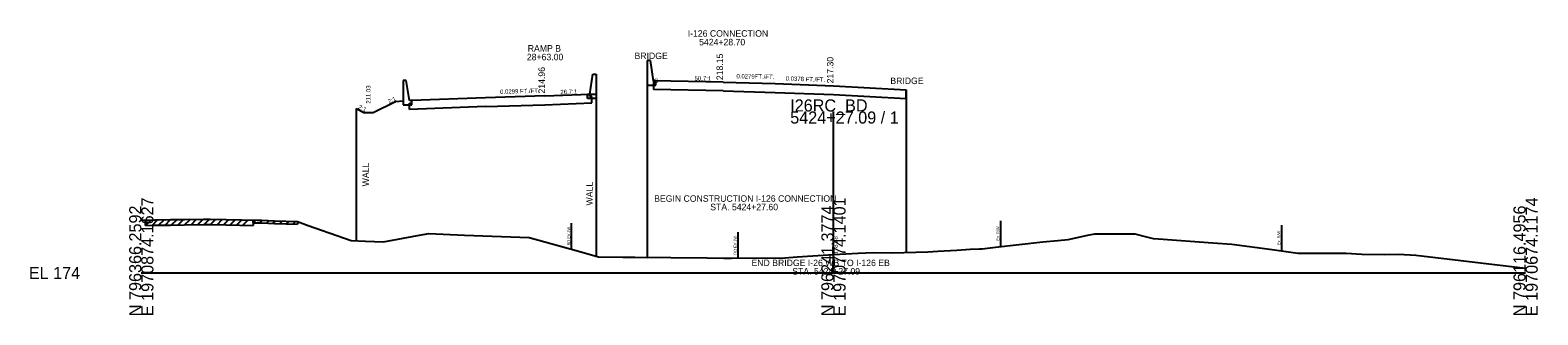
# Model space of a CAD drawing. Extents: x -1417 to 1970873, y -510 to 796304.
# Drawn here: x -1417.4 to -1068.8, y -509.7 to -443.8 of the extents above; entities that cross this region are included whole.
import ezdxf

# ---------------------------------------------------------------- set-up
doc = ezdxf.new("R2010")
doc.units = 0
for name, color, linetype in [('RD_EX_BldgApp', 7, 'Continuous'), ('RD_EX_Conc', 7, 'Continuous'), ('RD_EX_RailRoad', 7, 'Continuous'), ('RD_HC_Cl', 7, 'Continuous'), ('RD_HC_Data', 7, 'Continuous'), ('RD_HC_Data_Tic', 7, 'Continuous'), ('RD_HC_Data_Tic_Rel', 7, 'Continuous'), ('RD_HC_TX_Sta50', 7, 'Continuous'), ('RD_PD_ALT1_LnLine', 7, 'Continuous'), ('RD_PD_ALT1_TrvlWay', 7, 'Continuous'), ('RD_PD_ALT3_CL', 7, 'Continuous'), ('RD_PD_ALT5_CL', 7, 'Continuous'), ('RD_PD_Final_Cl', 7, 'Continuous'), ('RD_PD_Final_LnLine', 7, 'Continuous'), ('RD_PD_Final_TrvlWay', 7, 'Continuous'), ('RD_PD_PaveShd', 7, 'Continuous'), ('RD_Sketch2', 7, 'Continuous'), ('RD_Sketch8', 7, 'Continuous'), ('RD_TX_RoadID', 7, 'Continuous')]:
    doc.layers.add(name, color=color, linetype=linetype)

msp = doc.modelspace()

# ---------------------------------------------------------------- linework, layer by layer
at = {"layer": 'RD_EX_Conc'}
for p, q in [((-1273.99, -450.87), (-1274.74, -450.87)), ((-1274.74, -450.87), (-1274.74, -456.53)), ((-1273.24, -455.53), (-1273.99, -450.87)), ((-1330.41, -455.44), (-1331.16, -455.44)), ((-1331.16, -455.44), (-1331.16, -461.1)), ((-1329.66, -460.1), (-1330.41, -455.44)), ((-1288.02, -458.65), (-1287.27, -453.98)), ((-1287.27, -453.98), (-1286.52, -453.98)), ((-1286.52, -453.98), (-1286.52, -459.65)), ((-1274.74, -456.53), (-1272.74, -456.53)), ((-1272.74, -455.53), (-1273.24, -455.53)), ((-1272.74, -456.53), (-1272.74, -455.53)), ((-1288.52, -459.65), (-1288.52, -458.65)), ((-1288.52, -458.65), (-1288.02, -458.65)), ((-1286.52, -459.65), (-1288.52, -459.65)), ((-1331.16, -461.1), (-1329.16, -461.1)), ((-1329.16, -460.1), (-1329.66, -460.1)), ((-1329.16, -461.1), (-1329.16, -460.1))]:
    msp.add_line(p, q, dxfattribs=at)
at = {"layer": 'RD_HC_Cl'}
for p, q in [((-1231.67, -500), (-1231.67, -462.64)), ((-1391.67, -500), (-1231.67, -500)), ((-1231.67, -500), (-1071.67, -500))]:
    msp.add_line(p, q, dxfattribs=at)
at = {"layer": 'RD_HC_Data'}
for p, q in [((-1390.67, -489.02), (-1390.67, -487.77)), ((-1365.84, -487.76), (-1365.84, -489.01)), ((-1365.84, -488.39), (-1365.84, -487.76)), ((-1390.67, -489.02), (-1388.52, -488.97)), ((-1388.52, -488.97), (-1384.93, -488.91)), ((-1384.93, -488.91), (-1381.71, -488.86)), ((-1381.71, -488.86), (-1377.33, -488.81)), ((-1377.33, -488.81), (-1376.29, -488.8)), ((-1376.29, -488.8), (-1375.74, -488.81)), ((-1375.74, -488.81), (-1372.05, -488.89)), ((-1372.05, -488.89), (-1365.84, -489.01)), ((-1365.84, -488.39), (-1364.89, -488.41)), ((-1364.89, -488.41), (-1363.78, -488.43)), ((-1363.78, -488.43), (-1360.91, -488.52)), ((-1360.91, -488.52), (-1355.54, -488.69)), ((-1355.54, -488.06), (-1355.54, -488.69))]:
    msp.add_line(p, q, dxfattribs=at)
at = {"layer": 'RD_HC_Data_Tic_Rel'}
for p, q in [((-1214.89, -457.6), (-1214.89, -495.22)), ((-1342.04, -461.97), (-1340.04, -462.97)), ((-1338.04, -462.97), (-1340.04, -462.97)), ((-1332.91, -460.4), (-1338.04, -462.97)), ((-1331.16, -460.26), (-1332.91, -460.4))]:
    msp.add_line(p, q, dxfattribs=at)
msp.add_lwpolyline([(-1286.52, -496.12), (-1285.98, -496.28), (-1274.74, -496.39)], dxfattribs=at)
at = {"layer": 'RD_HC_TX_Sta50'}
for p, q in [((-1390.67, -489.02), (-1389.39, -487.74)), ((-1389.17, -488.98), (-1387.9, -487.71)), ((-1387.67, -488.95), (-1386.4, -487.68)), ((-1386.17, -488.93), (-1384.9, -487.65)), ((-1384.67, -488.9), (-1383.41, -487.64)), ((-1383.17, -488.88), (-1381.91, -487.62)), ((-1381.67, -488.86), (-1380.41, -487.6)), ((-1380.17, -488.84), (-1378.91, -487.58)), ((-1378.67, -488.83), (-1377.41, -487.56)), ((-1377.17, -488.81), (-1375.92, -487.55)), ((-1375.67, -488.81), (-1374.45, -487.59)), ((-1374.17, -488.84), (-1372.95, -487.62)), ((-1372.67, -488.87), (-1371.45, -487.65)), ((-1371.17, -488.91), (-1369.95, -487.68)), ((-1369.67, -488.94), (-1368.45, -487.71)), ((-1368.17, -488.97), (-1366.95, -487.74)), ((-1365.84, -488.39), (-1365.21, -487.78)), ((-1364.29, -488.42), (-1363.66, -487.81)), ((-1362.75, -488.46), (-1362.12, -487.86)), ((-1361.2, -488.51), (-1360.58, -487.91)), ((-1359.66, -488.56), (-1359.03, -487.95)), ((-1358.11, -488.61), (-1357.49, -488)), ((-1356.57, -488.65), (-1355.94, -488.05))]:
    msp.add_line(p, q, dxfattribs=at)
at = {"layer": 'RD_PD_ALT1_LnLine'}
for p, q in [((-1193.08, -487.91), (-1193.08, -493.91)), ((-1128.12, -488.91), (-1128.12, -494.91))]:
    msp.add_line(p, q, dxfattribs=at)
at = {"layer": 'RD_PD_ALT1_TrvlWay'}
for p, q in [((-1292.28, -488.46), (-1292.28, -494.46)), ((-1253.8, -490.56), (-1253.8, -496.56))]:
    msp.add_line(p, q, dxfattribs=at)
at = {"layer": 'RD_PD_Final_Cl'}
msp.add_lwpolyline([(-1391.67, -487.8), (-1388.52, -487.72), (-1384.93, -487.66), (-1381.71, -487.61), (-1377.33, -487.56), (-1376.29, -487.55), (-1375.74, -487.56), (-1372.05, -487.64), (-1364.89, -487.78), (-1363.78, -487.8), (-1360.91, -487.9), (-1355.54, -488.06), (-1353.09, -489.03), (-1343.13, -492.48), (-1339.84, -492.63), (-1335.71, -492.82), (-1327.85, -491.3), (-1325.2, -490.86), (-1316.93, -491.27), (-1301.98, -491.78), (-1291.18, -494.77), (-1285.98, -496.28), (-1260.89, -496.53), (-1257.04, -496.57), (-1255.21, -496.57), (-1242.91, -496.51), (-1240.09, -496.24), (-1231.67, -495.72), (-1225.96, -495.38), (-1222.38, -495.27), (-1218.17, -495.31), (-1209.87, -495.09), (-1207.51, -494.96), (-1203.18, -494.72), (-1200.1, -494.53), (-1197.87, -494.41), (-1197.32, -494.39), (-1194.18, -494.04), (-1183.27, -492.81), (-1179.78, -492.47), (-1177.38, -492.26), (-1172.84, -491.28), (-1171.27, -490.95), (-1165.75, -490.94), (-1162.03, -490.93), (-1159.61, -491.54), (-1157.77, -492.02), (-1156.54, -492.08), (-1143.94, -493), (-1139.58, -493.32), (-1130.27, -494.6), (-1124.35, -495.44), (-1122.57, -495.44), (-1113.18, -495.43), (-1109.51, -495.66), (-1104.37, -495.72), (-1101.03, -495.64), (-1097.03, -495.89), (-1071.67, -498.9)], dxfattribs=at)
at = {"layer": 'RD_PD_Final_LnLine'}
for p, q in [((-1257.2, -455.85), (-1273.24, -455.53)), ((-1312.14, -459.45), (-1329.16, -460.1)), ((-1298.37, -459.04), (-1288.02, -458.65)), ((-1231.67, -456.7), (-1214.89, -457.6))]:
    msp.add_line(p, q, dxfattribs=at)
at = {"layer": 'RD_PD_Final_TrvlWay'}
for p, q in [((-1273.24, -455.53), (-1273.24, -457.57)), ((-1288.02, -459.21), (-1288.02, -458.65)), ((-1287.5, -459.19), (-1288.02, -459.21)), ((-1287.5, -460.67), (-1287.5, -459.19)), ((-1257.2, -457.89), (-1273.24, -457.57)), ((-1257.2, -457.89), (-1245.18, -458.23)), ((-1245.18, -458.23), (-1231.67, -458.74)), ((-1231.67, -458.74), (-1214.89, -459.64)), ((-1214.89, -459.64), (-1214.89, -457.6)), ((-1329.68, -460.68), (-1329.16, -460.66)), ((-1329.68, -462.16), (-1329.68, -460.68)), ((-1312.14, -461.49), (-1329.68, -462.16)), ((-1329.16, -460.66), (-1329.16, -460.1)), ((-1312.14, -461.49), (-1298.37, -461.08)), ((-1298.37, -461.08), (-1287.5, -460.67))]:
    msp.add_line(p, q, dxfattribs=at)
at = {"layer": 'RD_PD_PaveShd'}
for p, q in [((-1257.2, -455.85), (-1245.18, -456.19)), ((-1245.18, -456.19), (-1231.67, -456.7)), ((-1298.37, -459.04), (-1312.14, -459.45))]:
    msp.add_line(p, q, dxfattribs=at)
at = {"layer": 'RD_TX_RoadID'}
for p, q in [((-1274.74, -455.53), (-1274.74, -496.29)), ((-1288.52, -458.65), (-1286.52, -458.65)), ((-1286.52, -458.65), (-1286.52, -496.12)), ((-1342.04, -461.97), (-1342.04, -492.53))]:
    msp.add_line(p, q, dxfattribs=at)

# ---------------------------------------------------------------- texts
at = {"layer": 'RD_EX_BldgApp'}
msp.add_text('178.28', height=1, rotation=90, dxfattribs=at).set_placement((-1230.67, -495.72))
at = {"layer": 'RD_EX_RailRoad'}
for s, rotation, p in [('0.0279FT./FT.', 358.8697, (-1254.1, -454.97)), ('0.0378 FT./FT.', 358.0851, (-1242.72, -455.49)), ('211.03', 90, (-1338.7, -460.83)), ('2:1', 26.5651, (-1334.39, -460.87)), ('0.0299 FT./FT.', 1.7103, (-1308.72, -458.58)), ('2:1', 333.4349, (-1341.65, -461.91))]:
    msp.add_text(s, height=1, rotation=rotation, dxfattribs=at).set_placement(p)
at = {"layer": 'RD_HC_Cl'}
for s, p in [('I26RC_BD', (-1241.67, -462.64)), ('5424+27.09 / 1', (-1241.67, -465.44)), ('EL 174', (-1417.67, -501.4))]:
    msp.add_text(s, height=2.8, dxfattribs=at).set_placement(p)
for s, p in [('E 1970874.1627', (-1388.87, -510)), ('E 1970774.1401', (-1228.87, -510)), ('E 1970674.1174', (-1068.87, -510)), ('N 796366.2592', (-1391.67, -510)), ('N 796241.3774', (-1231.67, -510)), ('N 796116.4956', (-1071.67, -510))]:
    msp.add_text(s, height=2.8, rotation=90, dxfattribs=at).set_placement(p)
at = {"layer": 'RD_HC_Data_Tic'}
for s, p in [(' 218.15', (-1257.2, -455.95)), (' 214.96', (-1298.37, -459.04)), (' 217.30', (-1231.67, -456.7))]:
    msp.add_text(s, height=1.5, rotation=90, dxfattribs=at).set_placement(p)
at = {"layer": 'RD_PD_ALT1_LnLine'}
for p in [(-1193.33, -492.53), (-1128.37, -493.53)]:
    msp.add_text('Ex. R/W ', height=0.65, rotation=90, dxfattribs=at).set_placement(p)
at = {"layer": 'RD_PD_ALT1_TrvlWay'}
for p in [(-1292.53, -493.63), (-1254.05, -495.73)]:
    msp.add_text('RD EV JW ', height=0.65, rotation=90, dxfattribs=at).set_placement(p)
at = {"layer": 'RD_PD_ALT3_CL'}
for s, p in [('I-126 CONNECTION', (-1265.36, -445.34)), ('5424+28.70', (-1262.72, -447.34)), ('28+63.00', (-1302.54, -450.79)), ('RAMP B', (-1302.34, -448.79))]:
    msp.add_text(s, height=1.5, dxfattribs=at).set_placement(p)
at = {"layer": 'RD_PD_ALT5_CL'}
for s, rotation, p in [('50.7:1', 358.8697, (-1263.79, -455.47)), ('26.7:1', 2.1416, (-1294.78, -458.65))]:
    msp.add_text(s, height=1, rotation=rotation, dxfattribs=at).set_placement(p)
at = {"layer": 'RD_Sketch2'}
msp.add_text('G', height=1, dxfattribs=at).set_placement((-1273.22, -456.03))
at = {"layer": 'RD_Sketch8'}
for s, p in [('BRIDGE', (-1277.66, -450.52)), ('BRIDGE', (-1218.52, -456.3)), ('BEGIN CONSTRUCTION I-126 CONNECTION', (-1273.12, -483.53)), ('STA. 5424+27.60', (-1260.15, -485.49)), ('END BRIDGE I-26 WB TO I-126 EB', (-1250.62, -498.41)), ('STA. 5424+27.09', (-1241.19, -500.37))]:
    msp.add_text(s, height=1.5, dxfattribs=at).set_placement(p)
for p in [(-1339.04, -479.95), (-1287.31, -484.38)]:
    msp.add_text('WALL', height=1.5, rotation=90, dxfattribs=at).set_placement(p)

doc.saveas('drawing.dxf')
